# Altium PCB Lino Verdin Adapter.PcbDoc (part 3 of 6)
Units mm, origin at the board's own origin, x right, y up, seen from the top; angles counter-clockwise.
Board outline 69.6 x 35 mm, 8 copper layers (Top Layer, Mid 1, GND 1, Mid 2, Mid 3, GND 2, Mid 4, Bottom Layer), stack 1.198 mm thick; 208 components, 258 nets, 1063 pads, 1090 vias.
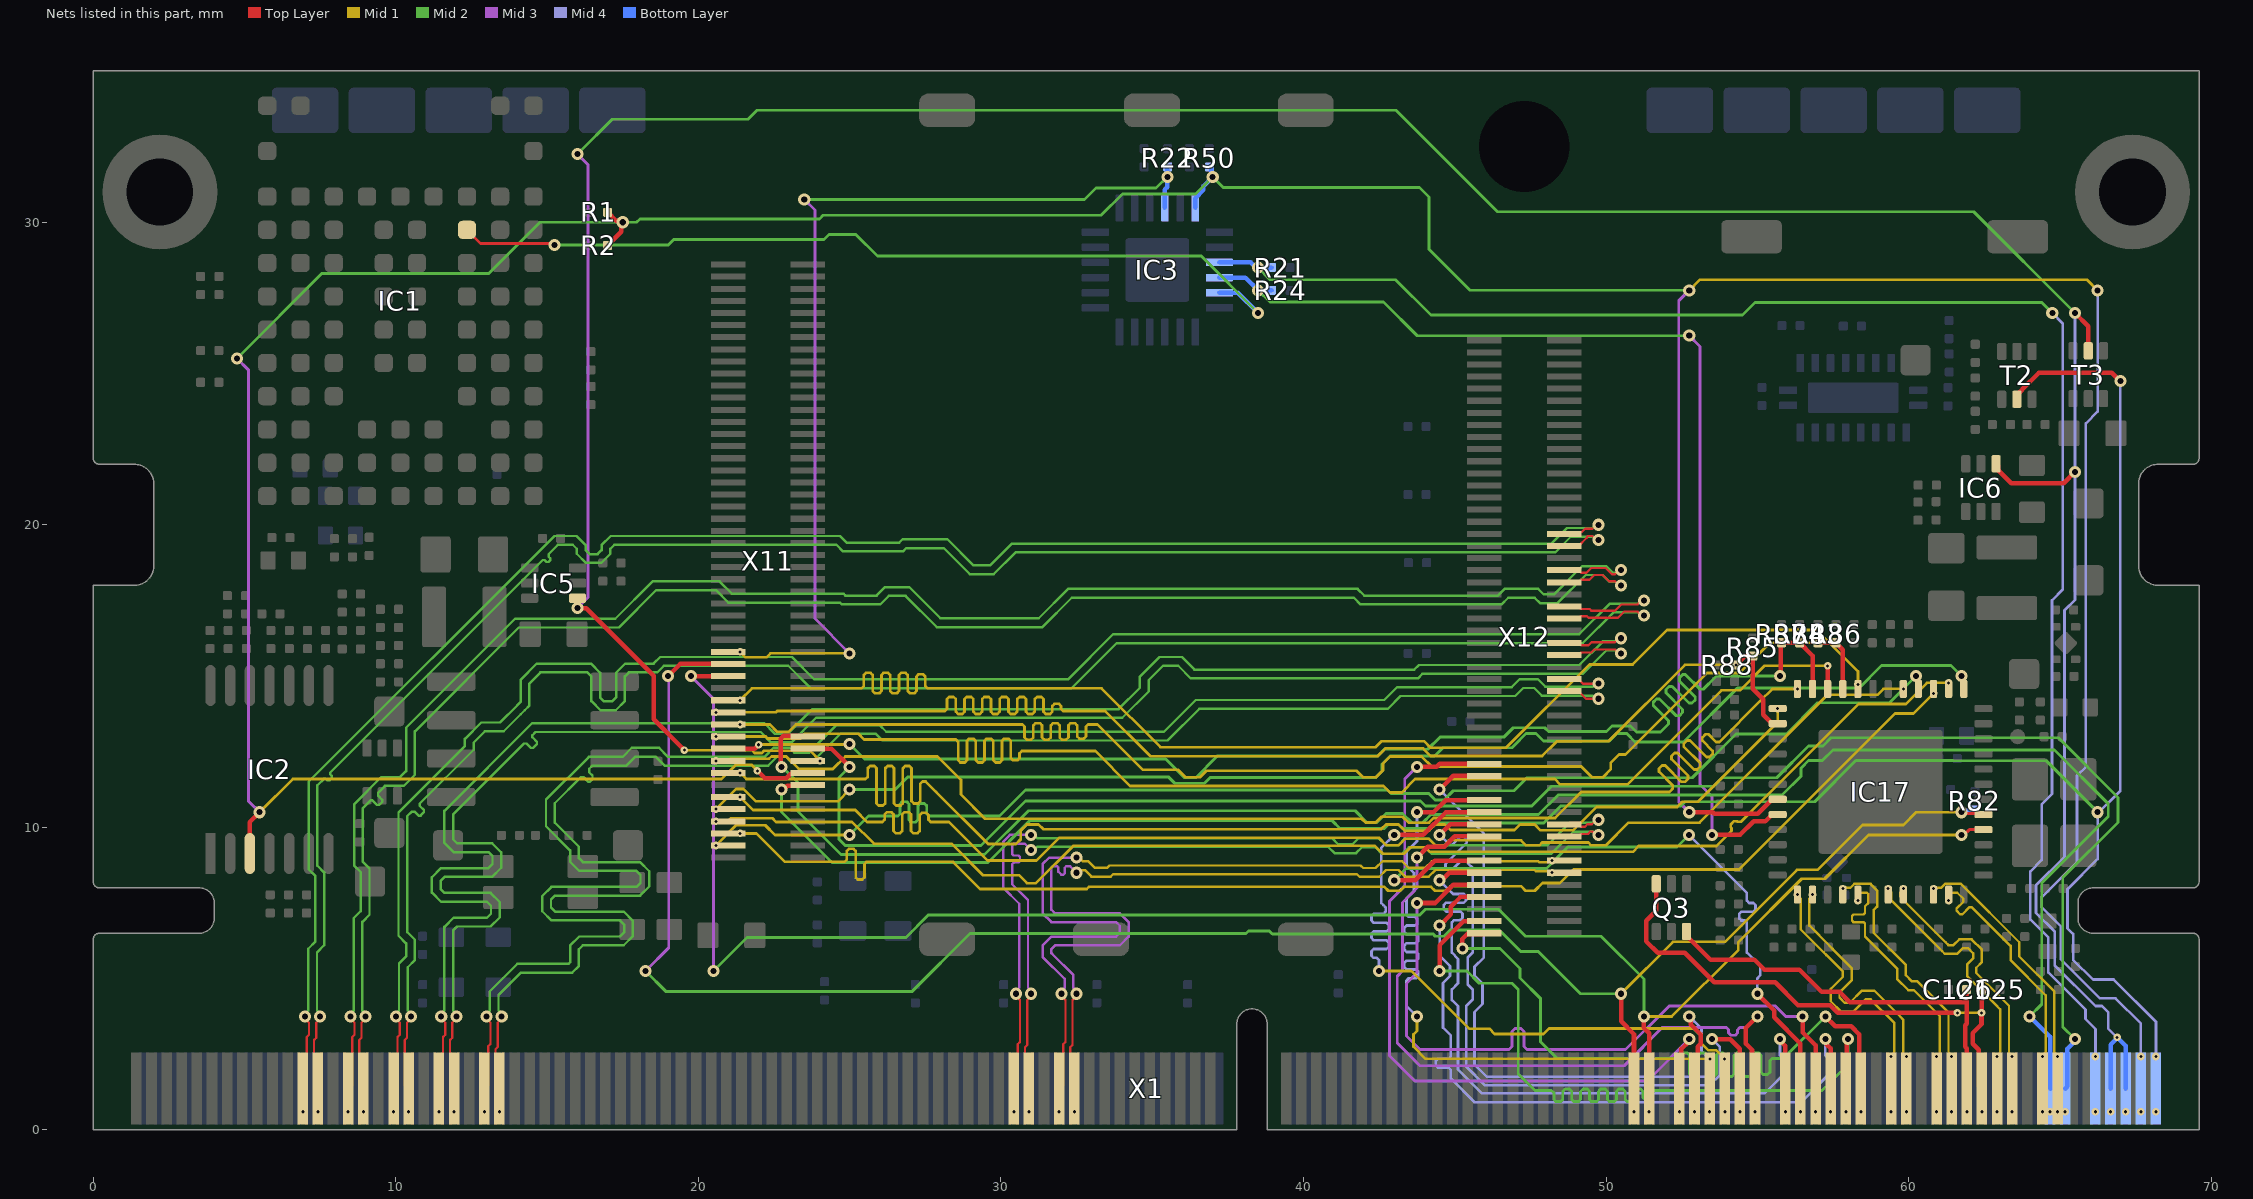
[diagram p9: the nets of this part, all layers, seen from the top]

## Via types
v1: diameter 0.4, hole 0.2, Top Layer to Bottom Layer, tented both sides, 600 vias
v2: diameter 0.25, hole 0.1, Mid 4 to Bottom Layer, tented both sides, 229 vias
v3: diameter 0.25, hole 0.1, Top Layer to Mid 1, tented both sides, 216 vias
v4: diameter 0.25, hole 0.1, Top Layer to Mid 1, tented top, 41 vias
v5: diameter 0.4, hole 0.2, Top Layer to Bottom Layer, 4 vias

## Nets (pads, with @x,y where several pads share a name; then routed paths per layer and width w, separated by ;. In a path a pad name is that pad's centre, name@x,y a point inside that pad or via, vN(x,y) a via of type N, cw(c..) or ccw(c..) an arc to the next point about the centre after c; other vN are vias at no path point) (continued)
CSI_1_D0_N: X1.125 X12.S90 | length 30
  Top Layer w0.075: X1.125@32.425,1.362 32.293,1.494 32.293,2.731 32.369,2.806 32.369,4.294 32.5,4.425 v1(32.5,4.5)
  Mid 3 w0.08: v1(32.5,4.5) 32.5,4.587 32.395,4.692 32.395,5.115 31.69,5.82 31.67,5.84 31.67,5.945 31.67,5.976 31.79,6.096 33.929,6.096 34.219,6.386 34.219,6.867 33.929,7.156 31.79,7.156 31.67,7.276 31.67,7.401 31.67,8.663 31.717,8.71 31.86,8.71 31.9,8.67 31.9,8.53 31.997,8.433 32.063,8.433 32.11,8.48 32.11,8.663 32.157,8.71 32.29,8.71 v1(32.5,8.5)
  Mid 1 w0.08: v1(32.5,8.5) 32.587,8.5 32.673,8.586 32.773,8.586 32.989,8.37 33.63,8.37 33.71,8.45 41.77,8.45 41.855,8.365 42.506,8.365 42.731,8.59 43.141,8.59 43.361,8.37 44.139,8.37 44.359,8.59 47.641,8.59 47.676,8.555 48.119,8.555 48.174,8.5 v3(48.22,8.5)
  other v3: 32.425,0.6
CSI_1_D0_P: X1.123 X12.S88 | length 30
  Top Layer w0.075: X1.123@31.925,1.362 32.056,1.494 32.056,2.829 32.132,2.904 32.132,4.294 32,4.425 v1(32,4.5)
  Mid 3 w0.08: v1(32,4.5) 32,4.587 32.105,4.692 32.105,4.995 31.38,5.72 31.38,5.82 31.38,5.945 31.38,6.097 31.67,6.386 33.809,6.386 33.929,6.506 33.929,6.746 33.809,6.866 31.67,6.866 31.38,7.156 31.38,7.401 31.38,8.783 31.597,9 v1(32.5,9)
  Mid 1 w0.08: v1(32.5,9) 32.587,9 32.711,8.876 32.893,8.876 33.109,8.66 33.51,8.66 33.59,8.74 41.89,8.74 41.975,8.655 42.386,8.655 42.611,8.88 43.261,8.88 43.481,8.66 44.019,8.66 44.239,8.88 47.761,8.88 47.796,8.845 48.119,8.845 48.174,8.9 v3(48.22,8.9)
  other v3: 31.925,0.6
CSI_1_D1_N: X1.119 X12.S84 | length 30.4
  Top Layer w0.075: X1.119@30.925,1.362 30.793,1.494 30.793,2.731 30.869,2.806 30.869,4.294 31,4.425 v1(31,4.5) ; X12.S84@48.62,9.7 49.09,9.7 49.171,9.781 49.401,9.781 49.481,9.862 49.55,9.862 49.662,9.75 v1(49.75,9.75)
  Mid 3 w0.08: v1(31,4.5) 31,4.587 30.895,4.692 30.895,7.595 30.37,8.12 30.37,8.78 30.43,8.84 30.583,8.84 30.63,8.887 30.63,9.023 30.583,9.07 30.42,9.07 30.37,9.12 30.37,9.413 30.417,9.46 30.79,9.46 v1(31,9.25)
  Mid 2 w0.08: v1(31,9.25) 31.087,9.25 31.192,9.355 40.82,9.355 41.025,9.15 41.74,9.15 41.93,9.34 42.381,9.34 42.601,9.12 43.261,9.12 43.481,9.34 44.019,9.34 44.239,9.12 48.18,9.12 48.915,9.855 49.558,9.855 49.663,9.75 v1(49.75,9.75)
  other v3: 30.925,0.6
CSI_1_D1_P: X1.117 X12.S82 | length 30.4
  Top Layer w0.075: X1.117@30.425,1.362 30.556,1.494 30.556,2.829 30.632,2.904 30.632,4.294 30.5,4.425 v1(30.5,4.5) ; X12.S82@48.62,10.1 49.09,10.1 49.171,10.019 49.303,10.019 49.383,10.099 49.524,10.099 49.675,10.25 v1(49.75,10.25)
  Mid 3 w0.08: v1(30.5,4.5) 30.5,4.587 30.605,4.692 30.605,7.475 30.08,8 30.08,9.533 30.297,9.75 v1(31,9.75)
  Mid 2 w0.08: v1(31,9.75) 31.087,9.75 31.192,9.645 40.94,9.645 41.145,9.44 41.62,9.44 41.81,9.63 42.501,9.63 42.721,9.41 43.141,9.41 43.361,9.63 44.139,9.63 44.359,9.41 48.06,9.41 48.795,10.145 49.558,10.145 49.663,10.25 v1(49.75,10.25)
  other v3: 30.425,0.6
CTRL_EN_WIFI: IC1.J3 IC3.5 | length 29.1
  Top Layer w0.1: IC1.J3@12.35,29.75 12.8,29.3 15.2,29.3 v1(15.25,29.25)
  Mid 2 w0.095: v1(15.25,29.25) 19.003,29.25 19.185,29.433 24.154,29.433 24.319,29.597 25.203,29.597 25.92,28.88 36.62,28.88 v1(38.5,27)
  Bottom Layer w0.15: IC3.5@37.22,27.672 37.828,27.672 v1(38.5,27)
CTRL_IO_EXP_INT_B: IC3.22 R22.1 X11.P65 | length 33.1
  Mid 3 w0.095: v1(23.5,30.75) 23.85,30.4 23.85,16.9 v1(25,15.75)
  Mid 2 w0.095: v1(23.5,30.75) 32.759,30.75 33.139,31.13 35.13,31.13 v1(35.5,31.5)
  Mid 1 w0.09: v3(21.38,15.8) 21.56,15.62 22.25,15.62 22.38,15.75 v1(25,15.75)
  Bottom Layer w0.15: IC3.22@35.42,30.472 35.42,31.08 35.5,31.16 v1(35.5,31.5) 35.505,31.505 35.505,31.825 R22.1@35.51,31.83
CTRL_PWR_BTN_MICO#: X1.248 X11.P82 | length 59.6
  Top Layer w0.15: X11.P82@23.62,12.6 24.4,12.6 v1(25,12)
  Mid 2 w0.095: v1(25,12) 24.653,11.653 24.653,9.606 24.856,9.403 29.343,9.403 30.81,10.87 43.871,10.87 44.034,10.707 47.547,10.707 48.2,11.36 53.551,11.36 53.831,11.64 55.64,11.64 56.69,12.69 57.17,12.69 57.44,12.96 64.95,12.96 66.92,10.99 66.92,10.16 65.098,8.338 65.098,3.402 v1(65.5,3)
  Bottom Layer w0.15: X1.248@65.175,1.362 65.243,1.43 65.243,2.675 65.5,2.932 v1(65.5,3)
  other v2: 65.175,0.6
CTRL_PWR_EN_MOCI: IC5.4 IC6.4 T3.5 X1.254 X1.256 X11.P84 | length 113.4
  Top Layer w0.15: IC5.4@16.006,17.573 16,17.567 v1(16,17.25) 16.011,17.239 16.291,17.239 18.52,15.01 18.52,13.57 v4(19.54,12.55) ; IC6.4@62.89,22.017 62.965,21.942 62.965,21.805 63.395,21.375 65.125,21.375 v1(65.5,21.75) ; v1(65.5,27) 65.939,26.561 T3.5@65.939,25.751
  Mid 3 w0.095: v1(16,17.25) 16.348,17.598 16.348,31.902 v1(16,32.25)
  Mid 2 w0.095: v1(16,32.25) 16.07,32.25 16.07,32.32 17.153,33.403 21.635,33.403 21.933,33.7 43.063,33.7 46.415,30.347 62.153,30.347 v1(65.5,27)
  Mid 4 w0.09: v1(65.5,27) v1(65.5,21.75) 65.5,17.52 65.155,17.175 65.155,9.025 64.215,8.085 64.215,7.166 64.83,6.551 64.83,5.44 66.175,4.095 66.393,4.095 66.595,3.893 66.595,3.355 v2(66.89,3.06)
  Mid 1 w0.09: v4(19.54,12.55) 21.77,12.55 21.86,12.46 22.102,12.46 22.177,12.535 23.685,12.535 v3(24.02,12.2)
  Bottom Layer w0.15: X1.254@66.675,1.362 66.675,2.818 66.89,3.033 v2(66.89,3.06) 67.175,2.775 X1.256@67.175,1.362
  other v2: 66.675,0.6 67.175,0.6
CTRL_RECOVERY_MICO#: X1.246 X11.P80 | length 61.2
  Top Layer w0.15: v1(22.75,12) 22.72,12.03 22.72,12.932 22.808,13.02 23.6,13.02 X11.P80@23.62,13
  Mid 2 w0.095: v1(22.75,12) 22.767,12 23.29,11.477 23.29,10.52 24.71,9.1 29.46,9.1 30.91,10.55 41.709,10.55 42.101,10.158 42.428,10.158 42.73,10.46 43.27,10.46 43.578,10.152 43.943,10.152 44.21,10.42 47.77,10.42 48.42,11.07 55.82,11.07 56.45,11.7 56.45,11.961 56.696,12.208 57.148,12.208 57.5,12.56 64.82,12.56 66.598,10.783 66.598,10.356 64.403,8.161 64.403,4.152 v1(64,3.75)
  Bottom Layer w0.15: v1(64,3.75) 64.675,3.075 X1.246@64.675,1.362
  other v2: 64.675,0.6
CTRL_RESET_MICO#: T2.5 X1.260 X11.P88 | length 77
  Top Layer w0.15: v1(22.75,11.25) 22.818,11.25 22.943,11.375 23.595,11.375 X11.P88@23.62,11.4 ; T2.5@63.579,24.148 63.579,24.283 63.754,24.458 63.754,24.475 64.309,25.03 66.72,25.03 v1(67,24.75)
  Mid 2 w0.095: v1(22.75,11.25) 22.75,10.51 24.42,8.84 29.57,8.84 30.95,10.22 40.95,10.22 41.208,9.962 42.676,9.962 42.811,10.097 43.144,10.097 43.284,9.957 44.216,9.957 44.399,10.14 47.94,10.14 48.5,10.7 52.459,10.7 52.606,10.848 56.896,10.848 58.256,12.208 61.464,12.208 61.471,12.2 64.55,12.2 v1(66.25,10.5)
  Mid 4 w0.09: v1@66.25,10.46 67,11.21 v1(67,24.75) ; v1(66.25,10.5) 66.25,8.95 65.255,7.955 65.255,6.664 65.44,6.479 65.44,5.622 66.092,4.97 66.78,4.97 68.175,3.575 v2(68.175,2.425)
  other v2: 68.175,0.6
CTRL_RESET_MOCI#: IC2.3 IC3.24 IC17.43 R1.2 R2.2 R50.1 X1.258 X11.P86 | length 154.4
  Top Layer w0.15: IC2.3@5.175,9.137 5.175,10.175 v1(5.5,10.5) ; R2.2@17,29.237 17.452,29.689 17.452,29.952 v1(17.5,30) 17.452,30.048 17.277,30.048 R1.2@17,30.325 ; v4(21.95,11.87) 21.955,11.87 22.2,11.625 22.905,11.625 23.055,11.775 23.595,11.775 X11.P86@23.62,11.8 ; v1(52.75,10.5) 53.526,10.5 53.581,10.445 54.568,10.445 54.573,10.45 55.02,10.45 55.495,10.925 IC17.43@55.675,10.925
  Mid 3 w0.095: v1(4.75,25.5) 5.125,25.125 5.125,10.875 v1(5.5,10.5) ; v1(52.75,10.5) 52.403,10.848 52.403,27.402 v1(52.75,27.75)
  Mid 2 w0.095: v1(4.75,25.5) 7.552,28.303 13.073,28.303 14.77,30 17.96,30 18.07,30.11 24.004,30.11 24.124,30.23 33.31,30.23 34.015,30.935 36.435,30.935 v1(37,31.5) 37.348,31.152 43.839,31.152 44.152,30.839 44.152,29.106 45.509,27.75 v1(52.75,27.75)
  Mid 4 w0.09: v1(66.25,27.75) 66.25,23.738 65.86,23.348 65.86,11.997 65.57,11.707 65.57,8.86 64.405,7.695 64.405,7.355 65.04,6.72 65.04,5.63 66.32,4.35 66.838,4.35 67.675,3.513 v2(67.675,2.425)
  Mid 1 w0.09: v1(5.5,10.5) 6.595,11.595 20.765,11.595 21.24,12.07 21.75,12.07 v4(21.95,11.87) ; v1(52.75,27.75) 53.095,28.095 65.905,28.095 v1(66.25,27.75)
  Bottom Layer w0.15: IC3.24@36.42,30.472 36.42,30.797 36.694,31.071 36.694,31.194 v1(37,31.5) 36.952,31.548 36.952,31.768 R50.1@36.89,31.83
  other v2: 67.675,0.6
CTRL_WAKE1_MICO#: IC3.3 R21.2 X1.252 | length 55.1
  Mid 2 w0.095: v1(38.5,28.5) 38.902,28.098 43.043,28.098 44.21,26.93 54.51,26.93 54.928,27.347 64.402,27.347 v1(64.75,27)
  Mid 4 w0.09: v1(64.75,27) 65.095,26.655 65.095,17.857 64.74,17.502 64.74,11.1 64.4,10.76 64.4,8.92 64.025,8.545 64.025,6.955 64.62,6.36 64.62,5.2 65.845,3.975 65.845,3.667 66.175,3.337 v2(66.175,2.425)
  Bottom Layer w0.15: IC3.3@37.22,28.672 38.261,28.672 38.432,28.5 v1(38.5,28.5) R21.2@38.95,28.5
  other v2: 66.175,0.6
DSI_1_CLK_N: X1.35 X12.S46 | length 59.6
  Top Layer w0.075: X1.35@9.925,1.362 10.057,1.494 10.057,3.07 10.131,3.145 10.131,3.544 10,3.675 v1(10,3.75) ; X12.S46@48.62,17.3 49.09,17.3 49.171,17.219 49.46,17.219 49.516,17.162 50.298,17.162 50.504,17.369 51.044,17.369 51.175,17.5 v1(51.25,17.5)
  Mid 2 w0.08: v1(10,3.75) 10,3.837 10.105,3.942 10.105,5.496 10.34,5.731 10.34,6.166 10.09,6.416 10.09,10.49 12.285,12.685 12.285,12.926 12.824,13.465 13.446,13.465 14.017,14.036 14.057,14.076 14.125,14.144 14.125,14.875 14.66,15.41 15.02,15.41 16.45,15.41 16.753,15.108 16.753,14.294 16.885,14.161 17.15,14.161 17.283,14.294 17.283,15.108 17.585,15.41 17.83,15.41 18.519,15.41 18.739,15.63 23.09,15.63 23.83,14.89 32.22,14.89 33.71,16.38 49.111,16.38 50.126,17.395 51.058,17.395 51.163,17.5 v1(51.25,17.5)
  other v3: 9.925,0.6
DSI_1_CLK_P: X1.37 X12.S48 | length 59.6
  Top Layer w0.075: X1.37@10.425,1.362 10.294,1.494 10.294,2.972 10.368,3.047 10.368,3.544 10.5,3.675 v1(10.5,3.75) ; X12.S48@48.62,16.9 49.09,16.9 49.172,16.982 49.362,16.982 49.418,16.925 50.397,16.925 50.603,17.132 51.044,17.132 51.175,17 v1(51.25,17)
  Mid 2 w0.08: v1(10.5,3.75) 10.5,3.837 10.395,3.942 10.395,5.376 10.63,5.611 10.63,6.286 10.38,6.536 10.38,10.37 10.53,10.52 10.62,10.52 10.752,10.388 10.818,10.388 10.932,10.502 10.932,10.568 10.788,10.712 10.788,10.778 12.575,12.565 12.575,12.805 12.945,13.175 13.566,13.175 14.13,13.739 14.262,13.871 14.415,14.024 14.415,14.755 14.78,15.12 15.02,15.12 16.33,15.12 16.463,14.988 16.463,14.173 16.765,13.871 17.27,13.871 17.573,14.173 17.573,14.988 17.705,15.12 17.83,15.12 18.639,15.12 18.859,15.34 22.97,15.34 23.71,14.6 32.34,14.6 33.83,16.09 49.231,16.09 50.246,17.105 51.058,17.105 51.163,17 v1(51.25,17)
  other v3: 10.425,0.6
DSI_1_D0_N: X1.47 X12.S58 | length 59.5
  Top Layer w0.075: X1.47@12.925,1.362 13.056,1.494 13.056,2.761 13.132,2.836 13.132,3.544 13,3.675 v1(13,3.75) ; X12.S58@48.62,14.9 49.09,14.9 49.24,14.75 v1(49.75,14.75)
  Mid 2 w0.08: v1(13,3.75) 13,3.837 13.105,3.942 13.105,4.575 14.02,5.49 15.713,5.49 15.76,5.537 15.76,5.73 15.76,6.09 16.062,6.393 17.413,6.393 17.546,6.525 17.546,6.79 17.413,6.923 15.142,6.923 14.84,7.225 14.84,7.73 15.142,8.033 17.955,8.033 18.088,8.165 18.088,8.43 17.955,8.563 16.062,8.563 15.76,8.865 15.76,9.11 15.76,9.24 14.965,10.035 14.965,10.915 16.38,12.33 17.5,12.33 17.8,12.63 18.7,12.63 19,12.33 22.189,12.33 22.489,12.63 23.011,12.63 23.171,12.47 23.66,12.47 24.57,13.38 25.99,13.38 26.21,13.16 35.391,13.16 36.441,14.21 42.67,14.21 43.09,14.63 46.88,14.63 47.145,14.895 47.746,14.895 47.996,14.645 49.558,14.645 49.663,14.75 v1(49.75,14.75)
  other v3: 12.925,0.6
DSI_1_D0_P: X1.49 X12.S60 | length 59.6
  Top Layer w0.075: X1.49@13.425,1.362 13.293,1.494 13.293,2.663 13.369,2.738 13.369,3.544 13.5,3.675 v1(13.5,3.75) ; X12.S60@48.62,14.5 48.665,14.455 49.135,14.455 49.34,14.25 v1(49.75,14.25)
  Mid 2 w0.08: v1(13.5,3.75) 13.5,3.837 13.395,3.942 13.395,4.455 14.14,5.2 15.833,5.2 16.05,5.417 16.05,5.73 16.05,5.97 16.183,6.103 17.533,6.103 17.836,6.405 17.836,6.91 17.533,7.213 15.262,7.213 15.13,7.345 15.13,7.61 15.262,7.743 18.075,7.743 18.378,8.045 18.378,8.55 18.075,8.853 16.183,8.853 16.05,8.985 16.05,9.11 16.05,9.25 16.05,9.36 15.255,10.155 15.255,10.795 16.12,11.66 16.2,11.66 16.352,11.508 16.418,11.508 16.5,11.59 16.5,11.71 16.395,11.815 16.395,11.935 16.5,12.04 17.62,12.04 17.92,12.34 18.58,12.34 18.88,12.04 22.309,12.04 22.609,12.34 22.891,12.34 23.051,12.18 23.78,12.18 24.69,13.09 25.87,13.09 26.09,12.87 35.511,12.87 36.561,13.92 42.79,13.92 43.21,14.34 47,14.34 47.265,14.605 47.626,14.605 47.876,14.355 49.558,14.355 49.663,14.25 v1(49.75,14.25)
  other v3: 13.425,0.6
DSI_1_D1_N: X1.41 X12.S52 | length 59.5
  Top Layer w0.075: X1.41@11.425,1.362 11.556,1.494 11.556,3.07 11.631,3.145 11.631,3.544 11.5,3.675 v1(11.5,3.75) ; X12.S52@48.62,16.1 49.09,16.1 49.171,16.019 49.416,16.019 49.517,16.119 50.294,16.119 50.425,16.25 v1(50.5,16.25)
  Mid 2 w0.08: v1(11.5,3.75) 11.5,3.837 11.605,3.942 11.605,3.97 11.605,4.9 11.605,6.71 11.907,7.013 13.013,7.013 13.146,7.145 13.146,7.41 13.013,7.543 11.494,7.543 11.192,7.845 11.192,8.35 11.494,8.653 13.063,8.653 13.195,8.785 13.195,9.05 13.063,9.183 11.907,9.183 11.605,9.485 11.605,9.73 11.605,10.545 14.5,13.44 22.18,13.44 22.52,13.1 22.96,13.1 23.77,13.91 33.891,13.91 34.595,14.614 34.595,14.986 35.239,15.63 35.98,15.63 36.395,15.215 43.662,15.215 43.812,15.365 49.115,15.365 49.895,16.145 50.308,16.145 50.413,16.25 v1(50.5,16.25)
  other v3: 11.425,0.6
DSI_1_D1_P: X1.43 X12.S54 | length 59.6
  Top Layer w0.075: X1.43@11.925,1.362 11.794,1.494 11.794,2.972 11.869,3.047 11.869,3.544 12,3.675 v1(12,3.75) ; X12.S54@48.62,15.7 49.09,15.7 49.171,15.782 49.515,15.782 49.615,15.882 50.294,15.882 50.425,15.75 v1(50.5,15.75)
  Mid 2 w0.08: v1(12,3.75) 12,3.837 11.895,3.942 11.895,4.9 11.895,6.59 12.027,6.723 13.133,6.723 13.436,7.025 13.436,7.53 13.133,7.833 11.614,7.833 11.482,7.965 11.482,8.23 11.614,8.363 13.183,8.363 13.485,8.665 13.485,9.17 13.183,9.473 12.027,9.473 11.895,9.605 11.895,9.73 11.895,10.425 14.24,12.77 14.32,12.77 14.467,12.623 14.533,12.623 14.667,12.757 14.667,12.823 14.513,12.977 14.513,13.043 14.62,13.15 22.06,13.15 22.4,12.81 23.08,12.81 23.89,13.62 34.011,13.62 34.885,14.494 34.885,14.866 35.359,15.34 35.86,15.34 36.275,14.925 43.783,14.925 43.933,15.075 49.235,15.075 50.015,15.855 50.308,15.855 50.413,15.75 v1(50.5,15.75)
  other v3: 11.925,0.6
DSI_1_D2_N: X1.29 X12.S40 | length 59.6
  Top Layer w0.075: X1.29@8.425,1.362 8.556,1.494 8.556,3.07 8.631,3.145 8.631,3.544 8.5,3.675 v1(8.5,3.75) ; X12.S40@48.62,18.5 49.09,18.5 49.171,18.419 49.356,18.419 49.512,18.574 49.988,18.574 50.194,18.369 50.294,18.369 50.425,18.5 v1(50.5,18.5)
  Mid 2 w0.08: v1(8.5,3.75) 8.5,3.837 8.605,3.942 8.605,6.996 8.84,7.231 8.84,8.519 8.62,8.739 8.62,10.76 9.52,11.66 10.141,11.66 10.34,11.859 10.34,13.29 13.945,16.895 17.254,16.895 18.489,18.13 20.7,18.13 21.11,17.72 24.799,17.72 24.859,17.66 25.891,17.66 26.171,17.94 26.97,17.94 28,16.91 31.25,16.91 32.22,17.88 41.79,17.88 42.01,17.66 46.43,17.66 46.65,17.88 47.761,17.88 47.941,17.7 48.28,17.7 49.21,18.63 50.011,18.63 50.227,18.414 50.327,18.414 50.413,18.5 v1(50.5,18.5)
  other v3: 8.425,0.6
DSI_1_D2_P: X1.31 X12.S42 | length 59.6
  Top Layer w0.075: X1.31@8.925,1.362 8.794,1.494 8.794,2.972 8.868,3.047 8.868,3.544 9,3.675 v1(9,3.75) ; X12.S42@48.62,18.1 49.09,18.1 49.172,18.182 49.454,18.182 49.61,18.337 49.89,18.337 50.096,18.132 50.294,18.132 50.425,18 v1(50.5,18)
  Mid 2 w0.08: v1(9,3.75) 9,3.837 8.895,3.942 8.895,6.876 9.13,7.111 9.13,8.639 8.91,8.859 8.91,10.64 9.162,10.892 9.228,10.892 9.382,10.738 9.448,10.738 9.552,10.842 9.552,10.908 9.41,11.05 9.41,11.14 9.64,11.37 10.261,11.37 10.63,11.739 10.63,13.17 14.065,16.605 17.374,16.605 18.609,17.84 20.58,17.84 20.99,17.43 24.679,17.43 24.739,17.37 26.011,17.37 26.291,17.65 26.85,17.65 27.88,16.62 31.37,16.62 32.34,17.59 41.67,17.59 41.89,17.37 46.55,17.37 46.77,17.59 47.641,17.59 47.821,17.41 48.4,17.41 49.33,18.34 49.891,18.34 50.107,18.124 50.289,18.124 50.413,18 v1(50.5,18)
  other v3: 8.925,0.6
DSI_1_D3_N: X1.23 X12.S34 | length 59.5
  Top Layer w0.075: X1.23@6.925,1.362 7.056,1.494 7.056,3.07 7.131,3.145 7.131,3.544 7,3.675 v1(7,3.75) ; X12.S34@48.62,19.7 48.682,19.763 49.2,19.763 49.306,19.868 49.544,19.868 49.675,20 v1(49.75,20)
  Mid 2 w0.08: v1(7,3.75) 7,3.837 7.105,3.942 7.105,5.989 7.34,6.224 7.34,8.393 7.12,8.613 7.12,11.511 15.239,19.63 15.69,19.63 15.97,19.63 16.273,19.328 16.273,19.163 16.405,19.031 16.67,19.031 16.803,19.163 16.803,19.328 17.105,19.63 17.35,19.63 24.68,19.63 24.9,19.41 26.641,19.41 26.751,19.52 28.23,19.52 29.09,18.66 29.641,18.66 30.361,19.38 48.2,19.38 48.715,19.895 49.558,19.895 49.663,20 v1(49.75,20)
  other v3: 6.925,0.6
DSI_1_D3_P: X1.25 X12.S36 | length 59.6
  Top Layer w0.075: X1.25@7.425,1.362 7.294,1.494 7.294,2.972 7.369,3.047 7.369,3.544 7.5,3.675 v1(7.5,3.75) ; X12.S36@48.62,19.3 49.09,19.3 49.36,19.57 49.36,19.588 49.404,19.631 49.544,19.631 49.675,19.5 v1(49.75,19.5)
  Mid 2 w0.08: v1(7.5,3.75) 7.5,3.837 7.395,3.942 7.395,5.869 7.63,6.104 7.63,8.513 7.41,8.733 7.41,11.391 7.621,11.602 7.688,11.602 7.742,11.548 7.808,11.548 7.887,11.627 7.887,11.693 7.833,11.747 7.833,11.814 14.855,18.835 14.915,18.835 14.98,18.77 15.05,18.77 15.1,18.82 15.1,18.9 15.055,18.945 15.055,19.035 15.359,19.34 15.69,19.34 15.85,19.34 15.983,19.208 15.983,19.043 16.285,18.741 16.79,18.741 17.093,19.043 17.093,19.208 17.225,19.34 17.35,19.34 24.56,19.34 24.78,19.12 26.761,19.12 26.871,19.23 28.11,19.23 28.97,18.37 29.761,18.37 30.481,19.09 48.32,19.09 48.835,19.605 49.558,19.605 49.663,19.5 v1(49.75,19.5)
  other v3: 7.425,0.6
ENET1_RD0: IC17.33 R83.1 R86.2 X11.P77 | length 45.1
  Top Layer w0.15: v3(57,16.1) R86.2@57.6,16.1 57.825,15.875 IC17.33@57.825,14.575
  Mid 1 w0.09: v3(21.38,13.4) 22.362,13.4 22.607,13.155 22.975,13.155 23.22,13.4 30.372,13.4 30.707,13.4 30.78,13.328 30.78,12.972 30.852,12.899 30.997,12.899 31.07,12.972 31.07,13.371 31.142,13.444 31.287,13.444 31.36,13.371 31.36,12.972 31.432,12.899 31.577,12.899 31.65,12.972 31.65,13.371 31.722,13.444 31.867,13.444 31.94,13.371 31.94,12.972 32.012,12.899 32.157,12.899 32.23,12.972 32.23,13.371 32.302,13.444 32.447,13.444 32.52,13.371 32.52,13.002 32.592,12.93 32.737,12.93 32.81,13.002 32.81,13.328 32.882,13.4 33.137,13.4 33.19,13.4 34.69,11.9 35.862,11.9 36.107,11.655 36.58,11.655 36.795,11.87 41.75,11.87 41.965,11.655 42.393,11.655 42.625,11.887 42.625,12.113 42.857,12.345 43.905,12.345 44.24,12.01 49.18,12.01 49.535,11.655 49.607,11.655 49.893,11.655 50.16,11.922 50.16,12.138 50.427,12.405 50.643,12.405 53.338,15.1 54.412,15.1 55.412,16.1 v3(57,16.1)
ENET1_RD1: IC17.34 X11.P79 | length 45.1
  Top Layer w0.15: IC17.34@57.325,14.575 v3(57.325,15.34)
  Mid 1 w0.09: v3(20.58,13) 22.23,13 22.29,12.94 23.37,12.94 23.525,13.095 25.285,13.095 25.48,12.9 28.18,12.9 28.515,12.9 28.588,12.828 28.588,12.219 28.66,12.147 28.805,12.147 28.878,12.219 28.878,12.858 28.95,12.93 29.095,12.93 29.168,12.858 29.168,12.219 29.24,12.147 29.385,12.147 29.458,12.219 29.458,12.858 29.53,12.93 29.675,12.93 29.748,12.858 29.748,12.219 29.82,12.147 29.965,12.147 30.038,12.219 30.038,12.858 30.11,12.93 30.255,12.93 30.328,12.858 30.328,12.286 30.4,12.213 30.545,12.213 30.618,12.286 30.618,12.448 30.69,12.52 31.55,12.52 33.12,12.52 34.27,11.37 42.642,11.37 42.857,11.155 43.252,11.155 43.692,11.595 48.307,11.595 48.482,11.42 50.71,11.42 53.82,14.53 54.43,14.53 55.245,15.345 57.32,15.345 v3(57.325,15.34)
ENET1_RD2: IC17.35 R84.1 R87.2 X11.P81 | length 45.2
  Top Layer w0.15: X11.P81@20.98,12.6 21.86,12.6 v4(21.99,12.73) ; v1(55.75,15) 55.775,15.025 55.775,16.075 R87.2@55.8,16.1 R84.1@56.4,16.1 56.825,15.675 IC17.35@56.825,14.575
  Mid 2 w0.095: v1(25,12.75) 25.49,12.26 35.45,12.26 36.057,11.653 36.443,11.653 37.15,12.36 42.46,12.36 42.68,12.58 44.11,12.58 44.51,12.98 46.62,12.98 46.932,13.292 47.978,13.292 48.1,13.17 50.018,13.17 50.198,13.35 50.81,13.35 51.008,13.152 51.802,13.152 52.035,13.385 52.069,13.419 52.069,13.523 51.56,14.031 51.56,14.135 51.665,14.24 51.769,14.24 52.321,13.687 52.426,13.687 52.53,13.792 52.53,13.896 51.978,14.448 51.978,14.553 52.082,14.657 52.186,14.657 52.739,14.105 52.843,14.105 52.947,14.209 52.947,14.313 52.423,14.837 52.423,14.942 52.527,15.046 52.631,15.046 53.112,14.566 53.216,14.566 53.623,14.973 53.65,15 v1(55.75,15)
  Mid 1 w0.09: v4(21.99,12.73) 22,12.74 24.99,12.74 v1(25,12.75)
ENET1_RD3: IC17.36 X11.P83 | length 45.1
  Mid 1 w0.09: v3(20.58,12.2) 21,12.2 21.07,12.27 22.34,12.27 22.415,12.345 22.905,12.345 23.32,11.93 24.442,11.93 24.857,12.345 27.905,12.345 28.68,11.57 28.68,11.082 29.477,10.285 41.925,10.285 42.05,10.16 42.388,10.16 42.578,10.35 43.28,10.35 43.475,10.155 44.148,10.155 44.303,10.31 48.32,10.31 49.18,11.17 52.091,11.17 52.175,11.253 52.206,11.285 52.206,11.388 51.752,11.842 51.752,11.944 51.855,12.047 51.957,12.047 52.501,11.503 52.603,11.503 52.706,11.606 52.706,11.708 52.162,12.252 52.162,12.355 52.265,12.457 52.367,12.457 52.911,11.913 53.013,11.913 53.116,12.016 53.116,12.119 52.572,12.662 52.572,12.765 52.675,12.867 52.777,12.867 53.321,12.324 53.423,12.324 53.526,12.426 53.526,12.529 53.183,12.872 53.183,12.974 53.285,13.077 53.388,13.077 53.642,12.823 53.744,12.823 55.091,14.169 55.496,14.575 v3(56.325,14.575)
ENET1_RX_CTL: IC17.38 R85.1 R88.2 X11.P75 | length 45.2
  Top Layer w0.15: v3(54.3,15.37) 54.583,15.653 54.843,15.653 R85.1@54.85,15.66 54.85,14.58 55.2,14.23 55.2,13.72 55.495,13.425 IC17.38@55.675,13.425
  Mid 1 w0.09: v3(20.58,13.8) 22.562,13.8 22.607,13.845 28.101,13.845 28.146,13.845 28.219,13.918 28.219,14.237 28.291,14.309 28.436,14.309 28.509,14.237 28.509,13.822 28.581,13.749 28.726,13.749 28.799,13.822 28.799,14.237 28.871,14.309 29.016,14.309 29.089,14.237 29.089,13.822 29.161,13.749 29.306,13.749 29.379,13.822 29.379,14.237 29.451,14.309 29.596,14.309 29.669,14.237 29.669,13.822 29.741,13.749 29.886,13.749 29.959,13.822 29.959,14.237 30.031,14.309 30.176,14.309 30.249,14.237 30.249,13.822 30.321,13.749 30.466,13.749 30.539,13.822 30.539,14.237 30.611,14.309 30.756,14.309 30.829,14.237 30.829,13.822 30.901,13.749 31.046,13.749 31.119,13.822 31.119,14.237 31.191,14.309 31.336,14.309 31.409,14.237 31.409,13.822 31.481,13.749 31.626,13.749 31.699,13.822 31.699,14.009 31.771,14.081 31.916,14.081 31.989,14.009 31.989,13.918 32.061,13.845 32.16,13.845 33.445,13.845 34.94,12.35 42.45,12.35 42.71,12.61 43.949,12.61 44.199,12.36 47.89,12.36 48.375,12.845 50.083,12.845 52.608,15.37 v3(54.3,15.37)
ENET1_RXC: IC17.32 X11.P73 | length 45
  Mid 1 w0.09: v3(21.38,14.2) 21.775,14.595 25.352,14.595 25.398,14.595 25.47,14.668 25.47,15.034 25.543,15.106 25.688,15.106 25.76,15.034 25.76,14.505 25.833,14.432 25.978,14.432 26.05,14.505 26.05,15.034 26.123,15.106 26.268,15.106 26.34,15.034 26.34,14.505 26.413,14.432 26.558,14.432 26.63,14.505 26.63,15.034 26.703,15.106 26.848,15.106 26.92,15.034 26.92,14.505 26.993,14.432 27.138,14.432 27.21,14.505 27.21,14.987 27.283,15.059 27.428,15.059 27.5,14.987 27.5,14.668 27.573,14.595 28.892,14.595 33.325,14.595 35.27,12.65 42.388,12.65 42.588,12.85 43.977,12.85 44.197,12.63 46.7,12.63 49.45,15.38 50.88,15.38 52.02,16.52 56.962,16.52 58.325,15.157 v3(58.325,14.725)
ENET1_TD0: IC17.28 X11.P97 | length 44.9
  Top Layer w0.1: IC17.28@60.325,14.575 60.325,15.085 v1@60.33,15.09
  Mid 2 w0.095: v1(25,9.75) 25.62,10.37 26.543,10.37 26.59,10.37 26.664,10.444 26.664,10.774 26.738,10.848 26.885,10.848 26.959,10.774 26.959,10.243 27.033,10.17 27.18,10.17 27.254,10.243 27.254,10.712 27.328,10.786 27.475,10.786 27.549,10.712 27.549,10.444 27.623,10.37 29.08,10.37 29.95,10.37 30.81,11.23 42.779,11.23 42.889,11.12 44.139,11.12 44.356,10.903 44.644,10.903 44.951,11.21 46.955,11.21 47.385,11.64 52.849,11.64 54.299,13.09 55.97,13.09 57,14.12 59.37,14.12 v1(60.25,15)
  Mid 1 w0.09: v3(20.58,9.4) 21.25,10.07 22.21,10.07 22.53,9.75 v1(25,9.75)
ENET1_TD1: IC17.27 X11.P95 | length 45
  Mid 1 w0.09: v3(21.38,9.8) 21.92,9.8 22.86,8.86 24.79,8.86 24.835,8.86 24.908,8.932 24.908,9.216 24.98,9.288 25.125,9.288 25.198,9.216 25.198,8.346 25.27,8.273 25.415,8.273 25.488,8.346 25.488,8.788 25.56,8.86 27.08,8.86 28.42,8.86 29.315,7.965 32.835,7.965 32.905,8.035 42.673,8.035 42.803,7.905 43.192,7.905 43.322,8.035 44.215,8.035 44.345,7.905 44.715,7.905 44.86,8.05 47.2,8.05 47.345,7.905 47.643,7.905 47.898,8.16 48.48,8.16 48.93,8.61 54.4,8.61 59.555,13.765 60.165,13.765 v3(60.825,14.425)
ENET1_TD2: IC17.26 X11.P93 | length 44.9
  Mid 1 w0.09: v3(20.58,10.2) 20.98,10.2 21.08,10.3 22.45,10.3 22.57,10.18 25.08,10.18 25.8,9.46 28.36,9.46 29.4,8.42 30.592,8.42 30.857,8.155 31.155,8.155 32.39,9.39 42.36,9.39 42.62,9.13 43.33,9.13 43.545,9.345 44.025,9.345 44.18,9.19 50.89,9.19 51.08,9.38 53.65,9.38 54.115,9.845 54.147,9.877 54.147,9.979 54.126,10.001 54.126,10.103 54.228,10.206 54.331,10.206 54.352,10.184 54.454,10.184 55.22,10.95 58.35,14.08 59.91,14.08 60.605,14.775 v3(61.325,14.775)
ENET1_TD3: IC17.25 X11.P91 | length 44.8
  Top Layer w0.15: v1(61.75,15) 61.788,14.962 61.788,14.613 IC17.25@61.825,14.575
  Mid 2 w0.095: v1(25,11.25) 26.51,11.25 26.93,11.67 35.53,11.67 35.742,11.458 36.728,11.458 36.92,11.65 42.391,11.65 42.598,11.856 42.598,12.089 42.869,12.36 44.34,12.36 44.61,12.63 46.894,12.63 46.949,12.686 46.949,12.691 47.356,13.097 47.683,13.097 47.93,12.85 50.109,12.85 50.356,13.097 50.684,13.097 50.961,12.82 52.56,12.82 54.34,14.6 58.36,14.6 59.108,15.348 61.403,15.348 v1(61.75,15)
  Mid 1 w0.09: v3(20.58,10.6) 21.25,11.27 21.492,11.27 21.902,10.86 24.61,10.86 v1(25,11.25)
ENET1_TX_CTL: IC17.37 X11.P85 | length 45.1
  Mid 1 w0.09: v3(21.38,11.8) 21.585,11.595 25.48,11.595 25.525,11.595 25.598,11.668 25.598,11.954 25.67,12.026 25.815,12.026 25.888,11.954 25.888,10.795 25.96,10.722 26.105,10.722 26.178,10.795 26.178,11.954 26.25,12.026 26.395,12.026 26.468,11.954 26.468,10.795 26.54,10.722 26.685,10.722 26.758,10.795 26.758,11.954 26.83,12.026 26.975,12.026 27.048,11.954 27.048,10.864 27.12,10.792 27.265,10.792 27.338,10.864 27.338,11.445 27.41,11.517 27.513,11.517 27.857,11.173 29.58,9.45 30.498,9.45 30.655,9.607 30.655,9.893 30.857,10.095 31.245,10.095 31.4,9.94 42.57,9.94 42.725,10.095 43.143,10.095 43.348,9.89 44.152,9.89 44.357,10.095 44.68,10.095 44.865,9.91 46.975,9.91 47.16,10.095 47.643,10.095 47.838,9.9 48.912,9.9 49.682,10.67 52.35,10.67 52.525,10.845 53.033,10.845 55.675,13.487 v3(55.675,13.925)
ENET1_TXC: IC17.29 X11.P89 | length 45.1
  Mid 1 w0.09: v3(21.38,11) 21.81,10.57 25.185,10.57 25.575,10.18 26.04,10.18 26.085,10.18 26.157,10.252 26.157,10.43 26.23,10.503 26.375,10.503 26.447,10.43 26.447,9.88 26.52,9.808 26.665,9.808 26.737,9.88 26.737,10.43 26.81,10.503 26.955,10.503 27.027,10.43 27.027,9.88 27.1,9.808 27.245,9.808 27.317,9.88 27.317,10.406 27.39,10.479 27.535,10.479 27.607,10.406 27.607,10.252 27.68,10.18 28.17,10.18 28.28,10.18 29.555,8.905 31.175,8.905 31.93,9.66 42.489,9.66 42.744,9.405 43.143,9.405 43.358,9.62 44.142,9.62 44.357,9.405 44.643,9.405 44.808,9.57 47.192,9.57 47.357,9.405 47.643,9.405 47.795,9.405 47.89,9.5 49.415,9.5 49.51,9.405 49.99,9.405 50.74,10.155 53.087,10.155 57.312,14.38 58.97,14.38 59.168,14.578 v3(59.828,14.578)
ENET_MDC: IC17.16 X1.193 X11.P69 | length 61.5
  Top Layer w0.1: v1(61.75,9.75) 61.831,9.75 62.006,9.925 IC17.16@62.475,9.925
  Top Layer w0.15: v1(19.75,15) X11.P69@20.98,15 ; v1(51.25,3.75) 51.25,3.37 51.425,3.195 X1.193@51.425,1.362
  Mid 3 w0.095: v1(19.75,15) 20.5,14.25 v1(20.5,5.25)
  Mid 2 w0.095: v1(20.5,5.25) 21.61,6.36 26.86,6.36 27.6,7.1 43.841,7.1 44.034,7.293 46.448,7.293 47.338,6.402 49.839,6.402 51.25,4.991 v1(51.25,3.75)
  Mid 1 w0.09: v1(51.25,3.75) 52.17,3.75 54.372,5.952 54.372,6.203 56.468,8.3 57.23,8.3 58.68,9.75 v1(61.75,9.75)
  other v3: 51.425,0.6
ENET_MDIO: IC17.17 R82.1 X1.191 X11.P67 | length 65.1
  Top Layer w0.1: v1(61.75,10.5) 61.787,10.463 62.438,10.463 IC17.17@62.475,10.425 62.539,10.489 IC17.17@62.603,10.425
  Top Layer w0.15: v1(19,15) 19.4,15.4 X11.P67@20.98,15.4 ; v1(50.5,4.5) 50.5,3.59 50.925,3.165 X1.191@50.925,1.362
  Mid 3 w0.095: v1(18.25,5.25) 19.02,6.02 19.02,14.98 v1(19,15)
  Mid 2 w0.095: v1(18.25,5.25) 18.92,4.58 27.071,4.58 28.981,6.49 38.1,6.49 38.18,6.57 38.87,6.57 38.97,6.47 44.289,6.47 44.356,6.402 44.644,6.402 44.851,6.61 46.47,6.61 47.18,5.9 47.76,5.9 49.16,4.5 v1(50.5,4.5)
  Mid 1 w0.09: v1(50.5,4.5) 52.215,6.215 53.935,6.215 56.315,8.595 56.995,8.595 58.48,10.08 59.828,10.08 60.248,10.5 v1(61.75,10.5)
  Bottom Layer w0.15: v1(61.75,10.5) 61.79,10.54 62.15,10.54 R82.1@62.19,10.58
  other v3: 50.925,0.6
ETH_1_ACT: C126.1 Q3.3 X1.235 | length 13.6
  Top Layer w0.15: Q3.3@52.66,6.555 52.66,6.42 53.455,5.625 54.905,5.625 55.23,5.3 56.39,5.3 57.13,4.56 57.72,4.56 58.06,4.22 61.922,4.22 ; C126.1@61.92,4.642 61.922,4.639 61.922,4.22 ; X1.235@61.925,1.362 61.922,1.365 61.922,2.694 61.875,2.741 61.875,3.457 61.922,3.504 61.922,4.22
  other v3: 61.925,0.6
ETH_1_INT#: IC3.4 IC17.44 R24.1 | length 36
  Top Layer w0.15: v1(53.5,9.75) 54.43,9.75 54.88,10.2 55.27,10.2 55.495,10.425 IC17.44@55.675,10.425
  Mid 3 w0.095: v1(52.75,26.25) 53.102,25.897 53.102,11.418 53.5,11.02 v1(53.5,9.75)
  Mid 2 w0.095: v1(38.5,27.75) 38.89,27.36 42.65,27.36 43.76,26.25 v1(52.75,26.25)
  Bottom Layer w0.15: IC3.4@37.22,28.172 38.078,28.172 v1(38.5,27.75) R24.1@38.95,27.75
ETH_1_LINK: C125.1 Q3.6 X1.237 | length 17.6
  Top Layer w0.15: Q3.6@51.66,8.135 51.66,7.239 51.335,6.914 51.335,6.228 51.713,5.85 52.6,5.85 53.575,4.875 55.595,4.875 56.345,4.125 57.405,4.125 57.66,3.87 v3(61.61,3.87) ; v4(62.41,3.87) 62.41,3.486 62.125,3.201 62.125,2.845 62.325,2.645 62.325,1.462 X1.237@62.425,1.362 ; C125.1@62.42,4.642 62.415,4.637 62.415,3.877 v4@62.422,3.87
  Mid 1 w0.09: v3(61.61,3.87) v4(62.41,3.87)
  other v3: 62.425,0.6
ETH_1_MDI0_N: IC17.2 X1.227 | length 8.2
  Mid 1 w0.08: v3(56.825,7.775) 56.825,7.748 56.72,7.643 56.72,6.75 57.4,6.07 57.488,5.982 58.118,5.352 58.118,4.942 57.716,4.541 57.716,4.371 57.886,4.201 58.055,4.201 58.457,4.603 58.867,4.603 59.747,3.723 59.82,3.65 59.82,3.62 59.82,2.557 59.925,2.452 v3(59.925,2.425)
  other v3: 59.925,0.6
ETH_1_MDI0_P: IC17.1 X1.225 | length 8.2
  Mid 1 w0.08: v3(56.325,7.775) 56.325,7.748 56.43,7.643 56.43,6.63 57.195,5.865 57.283,5.777 57.828,5.232 57.828,5.062 57.426,4.661 57.426,4.251 57.766,3.911 58.176,3.911 58.577,4.313 58.747,4.313 59.53,3.53 59.53,3.33 59.53,2.557 59.425,2.452 v3(59.425,2.425)
  other v3: 59.425,0.6
ETH_1_MDI1_N: IC17.5 X1.231 | length 8
  Mid 1 w0.08: v3(58.325,7.575) 58.292,7.608 58.292,7.712 58.277,7.727 58.277,7.793 58.324,7.84 58.623,7.84 58.67,7.793 58.67,7.501 58.56,7.391 58.56,7.167 58.513,7.12 58.177,7.12 58.13,7.073 58.13,6.917 58.177,6.87 58.513,6.87 58.56,6.823 58.56,6.39 59.62,5.33 59.62,4.989 59.989,4.62 60.17,4.62 61.03,3.76 61.03,2.557 60.925,2.452 v3(60.925,2.425)
  other v3: 60.925,0.6
ETH_1_MDI1_P: IC17.4 X1.233 | length 8
  Mid 1 w0.08: v3(57.825,7.975) 57.848,7.998 58.072,7.998 58.204,8.13 58.743,8.13 58.96,7.913 58.96,7.381 58.85,7.271 58.85,6.51 59.91,5.45 59.91,5.109 60.109,4.91 60.29,4.91 61.32,3.88 61.32,2.557 61.425,2.452 v3(61.425,2.425)
  other v3: 61.425,0.6
ETH_1_MDI2_N: IC17.8 X1.241 | length 8
  Mid 1 w0.08: v3(59.825,7.975) 59.825,7.948 59.72,7.843 59.72,7.705 61.228,6.198 61.316,6.109 61.486,6.109 61.673,6.296 62.083,6.296 62.422,5.957 62.422,5.547 62.235,5.36 62.235,5.19 62.974,4.451 63.063,4.363 63.32,4.105 63.32,2.557 63.425,2.452 v3(63.425,2.425)
  other v3: 63.425,0.6
ETH_1_MDI2_P: IC17.7 X1.239 | length 8
  Mid 1 w0.08: v3(59.325,7.975) 59.325,7.948 59.43,7.843 59.43,7.585 61.023,5.993 61.111,5.904 61.196,5.819 61.606,5.819 61.793,6.006 61.963,6.006 62.132,5.837 62.132,5.667 61.945,5.48 61.945,5.07 62.769,4.246 62.858,4.158 63.03,3.985 63.03,2.557 62.925,2.452 v3(62.925,2.425)
  other v3: 62.925,0.6
ETH_1_MDI3_N: IC17.11 X1.245 | length 8
  Mid 1 w0.08: v3(61.325,7.575) 61.292,7.608 61.292,7.712 61.277,7.727 61.277,7.793 61.324,7.84 61.61,7.84 61.81,7.64 61.81,7.54 61.583,7.313 61.583,7.247 61.707,7.123 61.773,7.123 62.015,7.365 62.085,7.365 63.37,6.08 63.37,5.611 64.53,4.451 64.53,2.557 64.425,2.452 v3(64.425,2.425)
  other v3: 64.425,0.6
ETH_1_MDI3_P: IC17.10 X1.247 | length 8
  Mid 1 w0.08: v3(60.825,7.975) 60.848,7.998 61.072,7.998 61.204,8.13 61.73,8.13 63.66,6.2 63.66,5.731 64.82,4.571 64.82,2.557 64.925,2.452 v3(64.925,2.425)
  other v3: 64.925,0.6
ETH_2_RGMII_RX_CTL: X1.199 X12.S73 | length 24.5
  Top Layer w0.15: v1(44.5,11.25) 44.95,11.7 X12.S73@45.98,11.7 ; v1(52.75,3.75) 52.798,3.702 52.798,3.482 53.125,3.155 53.125,2.845 53.025,2.745 53.025,1.462 X1.199@52.925,1.362
  Mid 4 w0.09: v1(44.5,11.25) 45.96,9.79 45.96,5.698 45.655,5.393 45.655,5.107 45.92,4.842 45.92,4.158 45.655,3.893 45.655,2.163 46.063,1.755 53.287,1.755 53.445,1.913 53.445,2.315 53.155,2.605 53.155,3.345 v1(52.75,3.75)
  other v3: 52.925,0.6
ETH_2_RGMII_RXC: X1.197 X12.S71 | length 24.8
  Top Layer w0.15: v1(43.75,12) 44.4,12 44.5,12.1 X12.S71@45.98,12.1 ; X1.197@52.425,1.362 52.493,1.43 52.493,2.675 52.75,2.932 v1(52.75,3)
  Mid 3 w0.095: v1(43.75,12) 43.348,11.598 43.348,8.068 42.84,7.56 42.84,5.401 42.843,5.399 42.843,5.111 42.84,5.109 42.84,4.651 42.848,4.644 42.848,2.453 43.68,1.62 51.37,1.62 v1(52.75,3)
  other v3: 52.425,0.6
ETH_2_RGMII_RXD0: X1.201 X12.S77 | length 24.4
  Top Layer w0.15: v1(43.75,10.5) 44.298,10.5 44.698,10.9 X12.S77@45.98,10.9 ; X1.201@53.425,1.362 53.425,2.335 v4(53.44,2.35)
  Mid 4 w0.09: v1(43.75,3.75) 43.405,4.095 43.405,4.357 43.405,4.605 43.405,4.65 43.405,4.94 43.477,5.013 43.72,5.013 43.793,5.085 43.793,5.23 43.72,5.303 43.404,5.303 43.332,5.375 43.332,5.52 43.404,5.593 43.72,5.593 43.793,5.665 43.793,5.81 43.72,5.883 43.404,5.883 43.332,5.955 43.332,6.1 43.404,6.173 43.72,6.173 43.793,6.245 43.793,6.39 43.72,6.463 43.404,6.463 43.332,6.535 43.332,6.68 43.404,6.753 43.686,6.753 43.758,6.825 43.758,6.97 43.686,7.043 43.477,7.043 43.405,7.115 43.405,7.178 43.405,7.223 43.405,7.643 43.65,7.888 43.65,8.486 43.405,8.731 43.405,9.195 43.75,9.54 v1(43.75,10.5)
  Mid 1 w0.09: v1(43.75,3.75) 43.75,3.27 43.64,3.16 43.64,2.75 44.04,2.35 v4(53.44,2.35)
  other v3: 53.425,0.6
ETH_2_RGMII_RXD1: X1.203 X12.S79 | length 23.4
  Top Layer w0.15: v1(43,9.75) 43.96,9.75 44.71,10.5 X12.S79@45.98,10.5
  Mid 4 w0.09: v1(42.495,5.255) 42.495,5.57 42.495,5.615 42.423,5.688 42.317,5.688 42.245,5.76 42.245,5.905 42.317,5.978 42.745,5.978 42.818,6.05 42.818,6.195 42.745,6.268 42.317,6.268 42.245,6.34 42.245,6.485 42.317,6.558 42.745,6.558 42.818,6.63 42.818,6.775 42.745,6.848 42.317,6.848 42.245,6.92 42.245,7.065 42.317,7.138 42.642,7.138 42.715,7.21 42.715,7.355 42.642,7.428 42.641,7.428 42.568,7.5 42.568,9.03 42.568,9.318 v1(43,9.75)
  Mid 1 w0.09: v1(42.495,5.255) 43.565,5.255 45.475,3.345 46.143,3.345 46.315,3.173 47.935,3.173 48.112,3.35 52.888,3.35 53.123,3.115 53.123,2.89 53.377,2.635 53.635,2.635 v4(53.92,2.35)
  other v3: 53.925,0.6
ETH_2_RGMII_RXD2: X1.205 X12.S81 | length 24.4
  Top Layer w0.15: v1(44.5,9.75) 44.85,10.1 X12.S81@45.98,10.1 ; v1(53.5,3) 54.11,3 54.423,2.687 54.423,1.365 X1.205@54.425,1.362
  Mid 4 w0.09: v1(44.5,9.75) 44.789,9.461 44.821,9.429 44.923,9.429 45.194,9.699 45.296,9.699 45.399,9.597 45.399,9.494 44.696,8.792 44.696,8.689 44.798,8.586 44.901,8.586 45.231,8.917 45.333,8.917 45.543,8.707 45.575,8.675 45.595,8.655 45.595,5.857 45.43,5.692 45.43,4.808 45.595,4.643 45.595,4.305 45.38,4.09 45.38,2.09 45.99,1.48 53.42,1.48 53.76,1.82 53.76,2.74 v1(53.5,3)
  other v3: 54.425,0.6
ETH_2_RGMII_RXD3: X1.207 X12.S83 | length 24.8
  Top Layer w0.15: v1(43.75,9) 44.11,9.36 44.661,9.36 45.001,9.7 X12.S83@45.98,9.7 ; X1.207@54.925,1.362 54.825,1.462 54.825,2.645 54.625,2.845 54.625,3.375 v1(55,3.75)
  Mid 3 w0.095: v1(43.75,9) 43.75,7.991 43.27,7.511 43.27,5.25 43.1,5.08 43.1,2.87 43.85,2.12 50.6,2.12 51.86,3.38 53.55,3.38 53.98,3.38 54.054,3.306 54.054,3.202 54.127,3.128 54.275,3.128 54.349,3.202 54.349,3.306 54.422,3.38 54.47,3.38 54.63,3.38 v1(55,3.75)
  other v3: 54.925,0.6
ETH_2_RGMII_TX_CTL: X1.211 X12.S89 | length 24.4
  Top Layer w0.15: v1(44.5,8.25) 44.568,8.25 44.818,8.5 X12.S89@45.98,8.5 ; v1(55.75,3) 55.75,2.95 55.925,2.775 X1.211@55.925,1.362
  Mid 4 w0.09: v1(44.5,8.25) 44.832,7.918 44.95,7.8 45.299,7.8 45.371,7.728 45.371,7.583 45.299,7.51 44.712,7.51 44.64,7.438 44.64,7.293 44.712,7.22 45.182,7.22 45.255,7.148 45.255,7.003 45.182,6.93 44.977,6.93 44.905,6.858 44.905,6.038 44.905,5.857 45.11,5.652 45.11,4.848 44.905,4.643 44.905,4.295 45.11,4.09 45.11,2 45.9,1.21 55.242,1.21 55.945,1.913 55.945,2.273 55.75,2.468 v1(55.75,3)
  other v3: 55.925,0.6
ETH_2_RGMII_TXC: X1.213 X12.S87 | length 24.4
  Top Layer w0.15: v1(43,8.25) 43.69,8.25 44.34,8.9 X12.S87@45.98,8.9 ; v1(55,4.5) 55.555,3.945 55.555,3.725 56.425,2.855 X1.213@56.425,1.362
  Mid 2 w0.095: v1(43,8.25) 43.39,8.64 48.03,8.64 48.738,9.348 52.348,9.348 v1(52.745,9.745)
  Mid 4 w0.09: v1(52.745,9.745) 54.655,7.835 54.655,7.62 54.655,7.575 54.727,7.502 54.868,7.502 54.941,7.43 54.941,7.285 54.868,7.212 54.473,7.212 54.4,7.14 54.4,6.995 54.473,6.922 54.582,6.922 54.655,6.85 54.655,6.33 54.655,5.857 55.095,5.417 55.095,5.107 55,5.012 v1(55,4.5)
  other v3: 56.425,0.6
ETH_2_RGMII_TXD0: X1.221 X12.S99 | length 26.1
  Top Layer w0.15: v1(45.25,6) 45.25,6.31 45.415,6.475 45.955,6.475 X12.S99@45.98,6.5 ; v1(57.25,3.75) 57.571,3.429 58.102,3.429 58.375,3.155 58.375,1.412 X1.221@58.425,1.362
  Mid 2 w0.095: v1(45.25,6) 46.491,6 47.153,5.339 47.153,5.023 47.84,4.336 47.84,2.91 48.39,2.36 52.345,2.36 52.392,2.36 52.466,2.434 52.466,2.468 52.54,2.542 52.687,2.542 52.761,2.468 52.761,1.844 52.835,1.77 52.982,1.77 53.056,1.844 53.056,2.468 53.13,2.542 53.277,2.542 53.351,2.468 53.351,1.844 53.425,1.77 53.572,1.77 53.646,1.844 53.646,2.468 53.72,2.542 53.867,2.542 53.941,2.468 53.941,1.844 54.015,1.77 54.162,1.77 54.236,1.844 54.236,2.468 54.31,2.542 54.457,2.542 54.531,2.468 54.531,1.844 54.605,1.77 54.752,1.77 54.826,1.844 54.826,2.468 54.9,2.542 55.047,2.542 55.121,2.468 55.121,1.905 55.195,1.831 55.342,1.831 55.416,1.905 55.416,2.286 55.49,2.36 55.78,2.36 55.86,2.36 v1(57.25,3.75)
  other v3: 58.425,0.6
ETH_2_RGMII_TXD1: X1.219 X12.S97 | length 26
  Top Layer w0.15: v1(44.5,5.25) 44.5,6.11 45.29,6.9 X12.S97@45.98,6.9 ; X1.219@57.925,1.362 57.962,1.4 57.962,2.962 v1(58,3)
  Mid 2 w0.095: v1(44.5,5.25) 45.41,5.25 45.813,4.848 46.894,4.848 47.1,4.641 47.1,1.85 47.65,1.3 47.86,1.3 48.203,1.3 48.276,1.226 48.276,1.006 48.35,0.933 48.498,0.933 48.571,1.006 48.571,1.273 48.645,1.347 48.793,1.347 48.866,1.273 48.866,1.006 48.94,0.933 49.088,0.933 49.161,1.006 49.161,1.273 49.235,1.347 49.383,1.347 49.456,1.273 49.456,1.006 49.53,0.933 49.678,0.933 49.751,1.006 49.751,1.273 49.825,1.347 49.973,1.347 50.046,1.273 50.046,1.006 50.12,0.933 50.268,0.933 50.341,1.006 50.341,1.273 50.415,1.347 50.563,1.347 50.636,1.273 50.636,1.006 50.71,0.933 50.858,0.933 50.931,1.006 50.931,1.273 51.005,1.347 51.153,1.347 51.226,1.273 51.226,1.059 51.3,0.985 51.448,0.985 51.521,1.059 51.521,1.226 51.595,1.3 52.17,1.3 57.14,1.3 58,2.16 v1(58,3)
  other v3: 57.925,0.6
ETH_2_RGMII_TXD2: X1.217 X12.S93 | length 24.4
  Top Layer w0.15: v1(44.5,6.75) 44.87,7.12 44.87,7.38 45.19,7.7 X12.S93@45.98,7.7 ; v1(57.25,3) 57.298,2.952 57.298,2.818 57.425,2.691 X1.217@57.425,1.362
  Mid 4 w0.09: v1(44.5,6.75) 44.5,5.76 44.845,5.415 44.845,5.085 44.61,4.85 44.61,3.378 44.87,3.118 44.87,2.66 44.87,2.42 44.798,2.348 44.448,2.348 44.375,2.275 44.375,2.13 44.448,2.058 44.798,2.058 44.87,1.985 44.87,1.94 44.87,1.7 45.66,0.91 56.442,0.91 57.445,1.913 57.445,2.273 57.25,2.468 v1(57.25,3)
  other v3: 57.425,0.6
ETH_2_RGMII_TXD3: X1.215 X12.S91 | length 24.8
  Top Layer w0.15: v1(43.75,7.5) 44.351,7.5 44.951,8.1 X12.S91@45.98,8.1 ; v1(56.5,3.75) 56.5,3.22 56.925,2.795 X1.215@56.925,1.362
  Mid 3 w0.095: v1(43.75,7.5) 43.75,5.191 43.402,4.844 43.402,3.106 43.856,2.652 46.27,2.652 46.795,2.652 46.894,2.751 46.894,3.249 46.992,3.347 47.19,3.347 47.289,3.249 47.289,2.751 47.387,2.652 47.83,2.652 50.644,2.652 52.089,4.098 55.592,4.098 55.94,3.75 v1(56.5,3.75)
  other v3: 56.925,0.6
